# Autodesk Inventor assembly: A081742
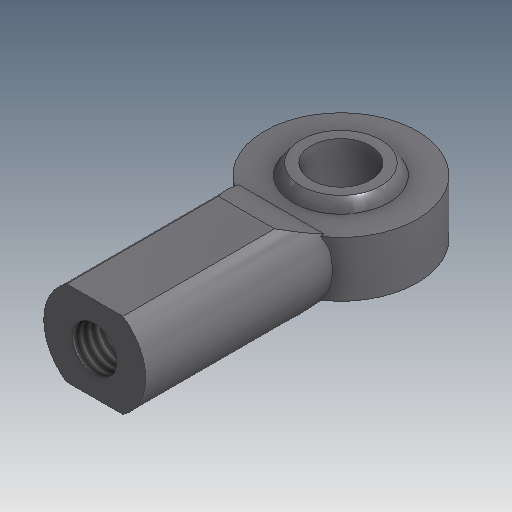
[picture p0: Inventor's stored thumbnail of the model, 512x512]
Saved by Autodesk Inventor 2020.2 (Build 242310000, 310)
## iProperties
Created: 1999-12
Part Number: A081742
Description: ROD-END,FEMALE,0.4375ID
Document SubType Name: Assembly
Designer: gpurviance
Mass: 102.426 g
Surface Area: 67.2204 cm^2
Volume: 13.0645 cm^3
Density: 7.84 g/cm^3
Control State: 0
Checked Out: False
Last Check In By: gpurviance
Master: False
Shininess: 0.0
Length Units: 11272
Angle Units: 11279
Time Units: 11290
Mass Units: 11286
Length Display Precision: 3
Angle Display Precision: 2
Compacted: True
Dimensions: 0,6x2,4x1,1 in
Mass: 0,226 lb
DocNumber: A081742.iam
Folder: 01 - Themengebiete\Simplification\01 - Packaging machine\
VDS_Category: 3D Komponenten
Density: 0.0
Volumn: 0.0
Area: 0.0
PropertySet Name: Model Information
Author: gpurviance
Revision Number: -
Title: ROD-END,FEMALE,0.4375ID
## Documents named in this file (3)
- D:\07 - DEMODATEN\OTX 2019 - Dataset - UPDATE - Dez2019\Designs\07-Packing machine\A081742.iam
- D:\07 - DEMODATEN\OTX 2019 - Dataset - UPDATE - Dez2019\Designs\07-Packing machine\Parts\ADSK-011721.ipt
- D:\07 - DEMODATEN\OTX 2019 - Dataset - UPDATE - Dez2019\Designs\07-Packing machine\Parts\ADSK-011722.ipt
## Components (2 placed, 2 different names)
1. ADSK-011722:1 — Angular, Passend:1, Passend:2
2. ADSK-011721:1 — Angular, Passend:1, Passend:2
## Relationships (3: Mate 2, Angle 1)
- Angular [Angle]: ADSK-011722:1 ↔ ADSK-011721:1
- Passend:1 [Mate]: ADSK-011722:1 ↔ ADSK-011721:1
- Passend:2 [Mate]: ADSK-011722:1 ↔ ADSK-011721:1
